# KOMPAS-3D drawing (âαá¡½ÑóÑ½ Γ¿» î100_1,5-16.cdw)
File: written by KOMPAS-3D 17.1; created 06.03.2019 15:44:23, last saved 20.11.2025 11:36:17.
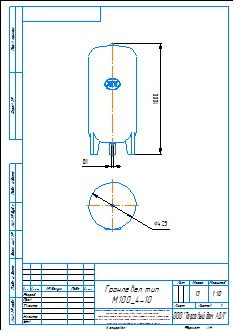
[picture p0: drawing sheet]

Sheet 1: A4, portrait

Title block, sheet 1: name: Гранлевел тип / М100_4-10; mass: 13; sheets: 1; sheet format: A4; stored path: C:\Users\kka\KOMPAS_Work\!Trash\ГРАНЛЕВЕЛ тип А Расширительный бак\KOMPAS 2D\Гранлевел тип А100_1,5-16.cdw

Views: Спереди 1, Спереди, Проекционный вид 2
Referenced files in C:\Users\mipv\Desktop\Тип А\SAT\: Гранлевел тип А100_4-10.a3d
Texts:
  kka
  adl
  Гранлевел тип А100_4-10
  Рама для чертежей
  Лит-Масса-Масштаб
  Материал-Предприятие
  Масштаб
  Изм.
  Лист
  № докум.
  Подп.
  Дата
  Лит.
  Разраб.
  Пров.
  Т.контр.
  Листов
  Внимание! Данный продукт является объектом авторского права ООО «Торговый Дом АДЛ».
  Запрещается изменение, копирование, распространение
  (в том числе путем копирования на другие сайты и ресурсы в Интернете)
  или любое иное использование информации и объектов без предварительного
  согласия правообладателя (ООО «Торговый Дом АДЛ»).
  Н.контр.
  Утв.
  ООО "Торговый дом АДЛ"
  Изменение
  Номер документа
  Подпись
  Обозначение документа
  Наименование изделия
  Масса изделия по ГОСТ 2.109-73
  Порядковый номер листа
  Общее количество листов в документе
  Характер работы, выполненной лицом, подписавшим документ
  Наименование или индекс предприятия, выпускающего документ
  Инв. № подл.
  Подп. и дата
  Взам. инв. №
  Инв. № дубл.
  Инвентарный номер подлинника по ГОСТ 2.501-68
  Подпись принявшего подлинник в отдел технической документации
  Инвентарный номер подлинника, взамен которого выпущен данный подлинник
  Инвентарный номер дубликата по ГОСТ 2.502-68
  Подпись принявшего дубликат в отдел технической документации
  Справ. №
  Перв. примен.
  Обозначение документа, взамен или на основании которого выпущен данный документ
  Обозначение документа, в котором впервые записан данный документ
  Подпись лица, копировавшего чертеж
  Обозначение формата листа
  !Рама для чертежа
Dimensions and other numbers on the sheet: 1000; 425; 1:10; 1; 13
